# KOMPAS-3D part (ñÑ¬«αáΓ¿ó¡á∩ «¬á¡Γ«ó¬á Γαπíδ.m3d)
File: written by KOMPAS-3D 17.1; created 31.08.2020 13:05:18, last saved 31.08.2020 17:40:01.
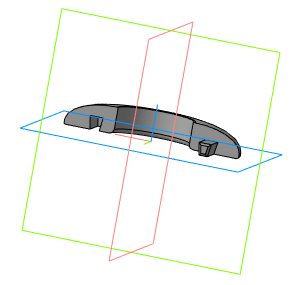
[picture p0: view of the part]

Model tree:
1. Эскиз:1
2. Элемент выдавливания:1
     Расстояние 1 = 6
3. Эскиз:2
4. Элемент выдавливания:2
     Расстояние 2 = 9
5. Эскиз:3
6. Элемент выдавливания:3
     Расстояние 1 = 8
7. Фаска:8
     Угол = 45; Длина 1 = 0.5; Длина 2 = 0.5
8. Скругление:1
     Полуось 1 = 5; Полуось 2 = 11
9. Скругление:2
     Радиус = 1
10. Скругление:3
     Радиус = 0.4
